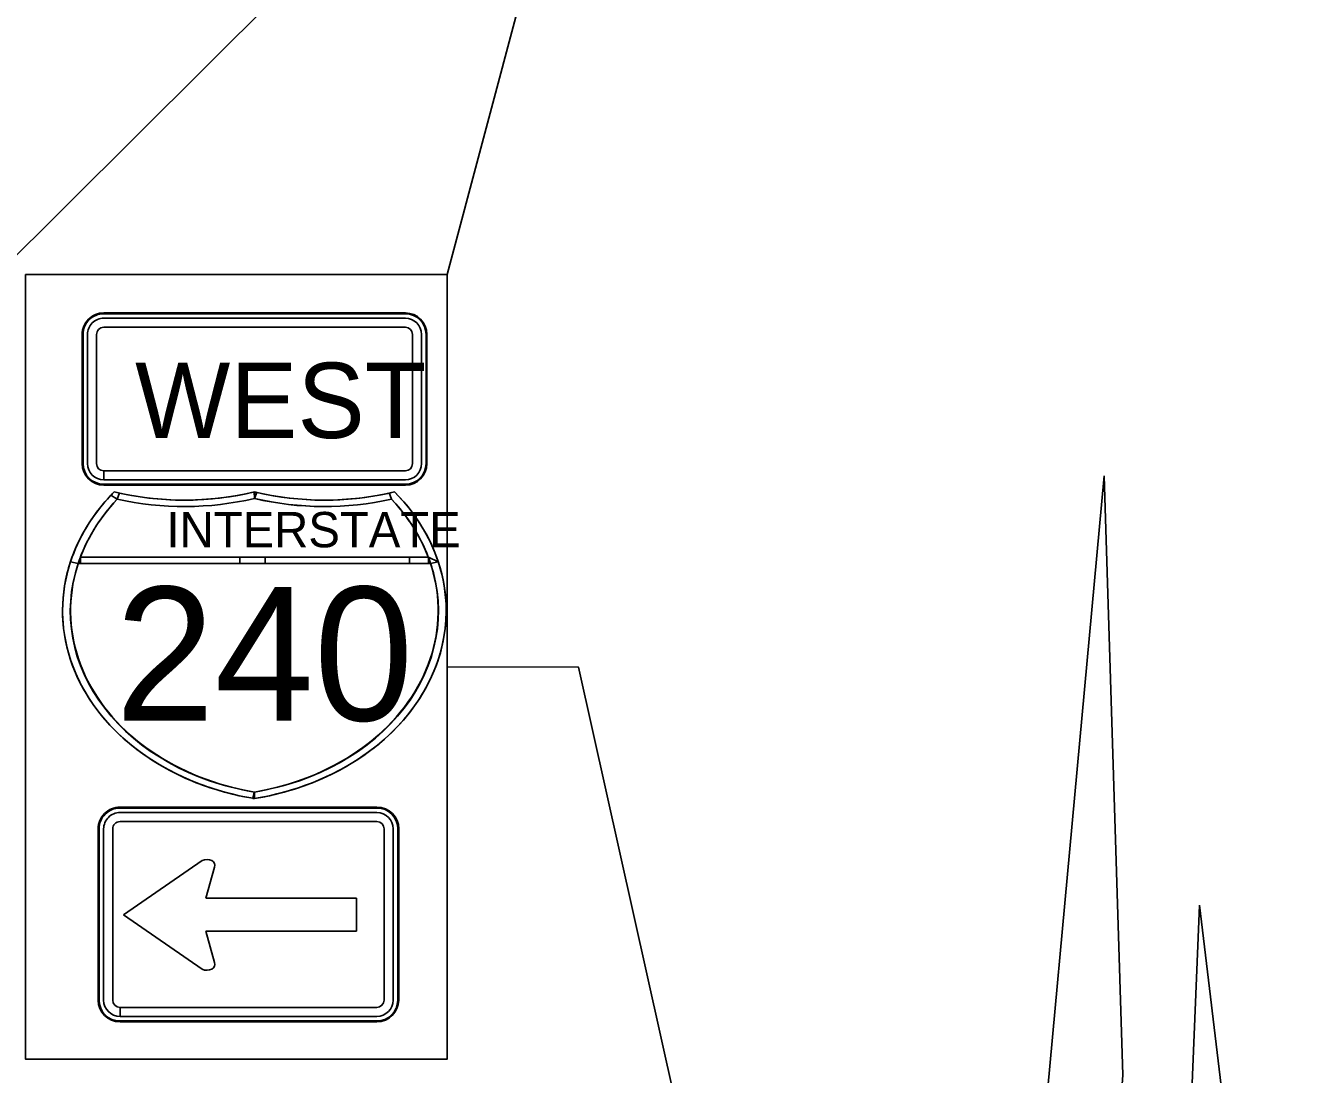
# Model space of a CAD drawing. Extents: x 886234 to 968767, y 455416 to 684046.
# Drawn here: x 915037 to 916508, y 471656 to 472874 of the extents above; entities that cross this region are included whole.
import ezdxf

# ---------------------------------------------------------------- set-up
doc = ezdxf.new("R2010")
doc.units = 0
for name, color, linetype in [('TC CONSTRUCTION PROPOSED ROADWAY SHADE', 7, 'Continuous'), ('TC DEV SIGN BLACK 239', 7, 'Continuous'), ('TC DEV SIGN BLACK ZERO', 7, 'Continuous'), ('TC DEV SIGN WHITE', 7, 'Continuous'), ('TC LABEL TEXT', 7, 'Continuous')]:
    doc.layers.add(name, color=color, linetype=linetype)

msp = doc.modelspace()

# ---------------------------------------------------------------- linework, layer by layer
at = {"layer": 'TC CONSTRUCTION PROPOSED ROADWAY SHADE'}
msp.add_lwpolyline([(915036.9, 472584.9), (915526.7, 472584.9), (915526.7, 471673.9), (915036.9, 471673.9)], close=True, dxfattribs=at)
at = {"layer": 'TC DEV SIGN BLACK 239'}
for p, q in [((915478, 472534.1), (915127.9, 472534.1)), ((915478, 472523.7), (915127.9, 472523.7)), ((915109.2, 472515.4), (915109.2, 472365.4)), ((915119.6, 472515.4), (915119.6, 472365.4)), ((915486.3, 472365.4), (915486.3, 472515.4)), ((915496.7, 472365.4), (915496.7, 472515.4)), ((915127.9, 472346.6), (915127.9, 472357)), ((915128, 472357), (915478, 472357)), ((915128, 472357), (915128, 472346.6)), ((915128, 472346.6), (915478, 472346.6)), ((915445, 471960.3), (915146.8, 471960.3)), ((915445, 471949.7), (915146.8, 471949.7)), ((915127.8, 471941.2), (915127.8, 471742.5)), ((915138.3, 471941.2), (915138.3, 471742.5)), ((915453.4, 471742.5), (915453.4, 471941.2)), ((915464, 471742.5), (915464, 471941.2)), ((915242.3, 471904.6), (915150.7, 471841.4)), ((915246.3, 471860.9), (915256.6, 471896.9)), ((915421.2, 471860.9), (915246.3, 471860.9)), ((915421.2, 471822.6), (915421.2, 471860.9)), ((915150.7, 471841.4), (915242.3, 471778.3)), ((915256.6, 471786), (915246.3, 471822.6)), ((915246.3, 471822.6), (915421.2, 471822.6)), ((915146.8, 471723.4), (915146.8, 471734)), ((915146.9, 471734), (915444.9, 471734)), ((915146.9, 471734), (915146.9, 471723.4)), ((915146.9, 471723.4), (915444.9, 471723.4))]:
    msp.add_line(p, q, dxfattribs=at)
for centre, major_axis, ratio, start_param, end_param in [((915127.9, 472515.4), (18.8, 0), 0.999865, 1.570796, 3.141593), ((915127.9, 472515.4), (8.33, 0), 0.999865, 1.570796, 3.141593), ((915478, 472515.4), (18.8, 0), 0.999865, 0, 1.570796), ((915478, 472515.4), (8.33, 0), 0.999865, 0, 1.570796), ((915127.9, 472365.4), (18.8, 0), 0.999865, 3.141593, 4.712389), ((915127.9, 472365.4), (8.33, 0), 0.999865, 3.141593, 4.712389), ((915478, 472365.4), (18.8, 0), 0.999865, 4.712389, 6.283185), ((915478, 472365.4), (8.33, 0), 0.999865, 4.712389, 6.283185), ((915146.8, 471941.2), (19, 0), 0.999865, 1.570796, 3.141593), ((915146.8, 471941.2), (8.45, 0), 0.999865, 1.570796, 3.141593), ((915445, 471941.2), (19, 0), 0.999865, 0, 1.570796), ((915445, 471941.2), (8.45, 0), 0.999865, 0, 1.570796), ((915247.6, 471899), (-9.44, 0), 0.720018, 2.830616, 5.313575), ((915247.6, 471783.9), (-9.44, 0), 0.720018, 0.969609, 3.452568), ((915146.8, 471742.5), (19, 0), 0.999865, 3.141593, 4.712389), ((915146.8, 471742.5), (8.45, 0), 0.999865, 3.141593, 4.712389), ((915444.9, 471742.5), (19, 0), 0.999865, 4.712389, 6.283185), ((915444.9, 471742.5), (8.45, 0), 0.999865, 4.712389, 6.283185)]:
    msp.add_ellipse(centre, major_axis=major_axis, ratio=ratio, start_param=start_param, end_param=end_param, dxfattribs=at)
at = {"layer": 'TC DEV SIGN BLACK ZERO'}
for p, q in [((915478, 472540.4), (915127.9, 472540.4)), ((915127.9, 472539.3), (915127.9, 472539.3)), ((915478, 472539.3), (915127.9, 472539.3)), ((915478, 472539.3), (915478, 472539.3)), ((915102.9, 472515.4), (915102.9, 472365.4)), ((915104, 472515.4), (915104, 472365.4)), ((915104, 472515.4), (915104, 472515.4)), ((915502, 472515.4), (915502, 472515.4)), ((915502, 472365.4), (915502, 472515.4)), ((915503, 472365.4), (915503, 472515.4)), ((915104, 472365.4), (915104, 472365.4)), ((915502, 472365.4), (915502, 472365.4)), ((915127.9, 472340.4), (915127.9, 472341.4)), ((915127.9, 472341.4), (915127.9, 472341.4)), ((915128, 472341.4), (915478, 472341.4)), ((915128, 472341.4), (915128, 472340.4)), ((915128, 472340.4), (915478, 472340.4)), ((915143.6, 472324.1), (915146.1, 472331.3)), ((915303, 472324.9), (915302.7, 472332.7)), ((915303, 472325.5), (915302.7, 472332.7)), ((915459.4, 472331.3), (915461.9, 472324.1)), ((915478, 472341.4), (915478, 472341.4)), ((915100.8, 472256.7), (915504.7, 472256.7)), ((915285.8, 472256.7), (915100.8, 472256.7)), ((915315.1, 472256.7), (915285.8, 472256.7)), ((915482.8, 472256.7), (915315.1, 472256.7)), ((915504.7, 472256.7), (915482.8, 472256.7)), ((915516.3, 472251.2), (915504.7, 472256.7)), ((915098.2, 472249.3), (915507.3, 472249.3)), ((915098.2, 472249.3), (915100.8, 472249.3)), ((915100.8, 472249.3), (915285.8, 472249.3)), ((915285.8, 472249.3), (915315.1, 472249.3)), ((915315.1, 472249.3), (915482.8, 472249.3)), ((915482.8, 472249.3), (915504.7, 472249.3)), ((915507.1, 472249.8), (915504.7, 472249.3)), ((915504.7, 472249.3), (915507.3, 472249.3)), ((915080.1, 472195.7), (915080.1, 472193.5)), ((915525.4, 472193.4), (915525.4, 472195.7)), ((915302.8, 471976.4), (915302.8, 471984)), ((915445, 471966.6), (915146.8, 471966.6)), ((915146.8, 471965.5), (915146.8, 471965.5)), ((915445, 471965.5), (915146.8, 471965.5)), ((915445, 471965.5), (915445, 471965.5)), ((915121.4, 471941.2), (915121.4, 471742.5)), ((915122.5, 471941.2), (915122.5, 471742.5)), ((915122.5, 471941.2), (915122.5, 471941.2)), ((915469.2, 471941.2), (915469.3, 471941.2)), ((915469.2, 471742.5), (915469.3, 471941.2)), ((915470.3, 471742.5), (915470.3, 471941.2)), ((915122.5, 471742.5), (915122.5, 471742.5)), ((915469.2, 471742.5), (915469.2, 471742.5)), ((915146.8, 471717.1), (915146.8, 471718.2)), ((915146.8, 471718.2), (915146.8, 471718.2)), ((915146.8, 471718.2), (915444.9, 471718.2)), ((915146.8, 471718.2), (915146.8, 471717.1)), ((915146.8, 471717.1), (915444.9, 471717.1)), ((915444.9, 471718.2), (915444.9, 471718.2))]:
    msp.add_line(p, q, dxfattribs=at)
for points in [[(915140.1, 472332.7), (915140.1, 472332.7), (915140.1, 472332.7)], [(915146.1, 472331.3), (915143.6, 472324.1)], [(915303, 472332.6), (915303, 472325.5), (915305.6, 472332)], [(915305.6, 472332), (915303, 472324.9)], [(915461.9, 472324.1), (915459.4, 472331.3)], [(915465.4, 472332.7), (915465.4, 472332.7), (915465.4, 472332.7)], [(915136.1, 472328.6), (915143.6, 472324.1)], [(915143.6, 472324.1), (915136.1, 472328.6)], [(915302.8, 472324.9), (915303, 472325.5)], [(915100.8, 472256.7), (915100.8, 472249.3)], [(915100.8, 472249.3), (915100.8, 472256.7)], [(915285.8, 472249.3), (915285.8, 472256.7)], [(915285.8, 472256.7), (915285.8, 472249.3)], [(915315.1, 472256.7), (915315.1, 472249.3)], [(915315.1, 472249.3), (915315.1, 472256.7)], [(915482.8, 472249.3), (915482.8, 472256.7)], [(915482.8, 472256.7), (915482.8, 472249.3)], [(915504.7, 472256.7), (915516.3, 472251.2)], [(915504.7, 472249.3), (915504.7, 472256.7)], [(915504.7, 472256.7), (915504.7, 472249.3), (915507.1, 472249.8), (915504.7, 472256.7)], [(915089.2, 472251.2), (915098.2, 472249.3)], [(915098.2, 472249.3), (915089.2, 472251.2)], [(915507.3, 472249.3), (915507.1, 472249.8)], [(915516.3, 472251.2), (915507.3, 472249.3)], [(915507.3, 472249.3), (915516.3, 472251.2)], [(915300.8, 471976.7), (915302.7, 471984)], [(915302.8, 471984), (915300.8, 471976.7), (915302.7, 471976.4)], [(915302.8, 471984), (915302.8, 471976.4)]]:
    msp.add_lwpolyline(points, dxfattribs=at)
for centre, major_axis, ratio, start_param, end_param in [((915127.9, 472515.4), (25, 0), 0.999865, 1.570796, 3.141593), ((915127.9, 472515.4), (24, 0), 0.999865, 1.570796, 3.141593), ((915478, 472515.4), (25, 0), 0.999865, 0, 1.570796), ((915478, 472515.4), (24, 0), 0.999865, 0, 1.570796), ((915127.9, 472365.4), (25, 0), 0.999865, 3.141593, 4.712389), ((915127.9, 472365.4), (24, 0), 0.999865, 3.141593, 4.712389), ((915478, 472365.4), (25, 0), 0.999865, 4.712389, 6.283185), ((915478, 472365.4), (24, 0), 0.999865, 4.712389, 6.283185), ((915358.4, 472194.6), (-278.3, 0), 0.800002, 5.614188, 7.652625), ((915358.4, 472194.6), (-278.3, 0), 0.800002, 5.614216, 5.637358), ((915221.4, 472545.6), (278.3, 0), 0.800002, 4.415792, 5.008922), ((915221.4, 472545.6), (278.3, 0), 0.800002, 4.415856, 4.438209), ((915221.4, 472545.6), (278.3, 0), 0.800002, 4.438209, 5.008909), ((915384.1, 472545.6), (278.3, 0), 0.800002, 4.415856, 5.008986), ((915247.1, 472194.6), (278.3, 0), 0.800002, 4.913746, 6.952183), ((915384.1, 472545.6), (278.3, 0), 0.800002, 4.416709, 4.426515), ((915384.1, 472545.6), (278.3, 0), 0.800002, 4.426515, 4.986569), ((915384.1, 472545.6), (278.3, 0), 0.800002, 4.986569, 5.008922), ((915247.1, 472194.6), (278.3, 0), 0.800002, 0.256966, 0.66897), ((915358.4, 472194.6), (-269, 0), 0.800002, 5.637358, 7.64558), ((915358.4, 472194.6), (-278.3, 0), 0.800002, 5.637358, 6.026219), ((915358.4, 472194.6), (-269, 0), 0.800002, 5.637358, 6.026219), ((915221.4, 472545.6), (287.6, 0), 0.800002, 4.438209, 4.999074), ((915221.4, 472545.6), (287.6, 0), 0.800002, 4.438209, 4.999074), ((915384.1, 472545.6), (287.6, 0), 0.800002, 4.425704, 4.986569), ((915247.1, 472194.6), (269, 0), 0.800002, 4.920791, 6.929013), ((915384.2, 472545.3), (287.2, 0), 0.800002, 4.425686, 4.986568), ((915247.1, 472194.6), (269, 0), 0.800002, 0.292795, 0.645828), ((915358.4, 472194.6), (-269, 0), 0.800002, 5.99039, 6.026219), ((915247.1, 472194.6), (269, 0), 0.800002, 0.256966, 0.292795), ((915357.1, 472193.9), (-268, 0), 0.800002, 6.022151, 7.649781), ((915358.4, 472194.6), (-278.3, 0), 0.800002, 6.026219, 6.278259), ((915248.4, 472193.9), (268, 0), 0.800002, 4.916934, 6.544356), ((915247.1, 472194.6), (278.3, 0), 0.800002, 0.005231, 0.256966), ((915358.4, 472194.6), (-278.3, 0), 0.800002, 0.004927, 1.362388), ((915247.1, 472194.6), (278.3, 0), 0.800002, 4.913748, 6.277955), ((915358.4, 472194.6), (-278.3, 0), 0.800002, 1.36935, 1.369438), ((915247.1, 472194.6), (269, 0), 0.800002, 4.920791, 4.921138), ((915247.1, 472194.6), (278.3, 0), 0.800002, 4.913747, 4.913748), ((915146.8, 471941.2), (25.4, 0), 0.999865, 1.570796, 3.141593), ((915146.8, 471941.2), (24.3, 0), 0.999865, 1.570796, 3.141593), ((915445, 471941.2), (25.4, 0), 0.999865, 0, 1.570796), ((915445, 471941.2), (24.3, 0), 0.999865, 0, 1.570796), ((915146.8, 471742.5), (25.4, 0), 0.999865, 3.141593, 4.712389), ((915146.8, 471742.5), (24.3, 0), 0.999865, 3.141593, 4.712389), ((915444.9, 471742.5), (25.4, 0), 0.999865, 4.712389, 6.283185), ((915444.9, 471742.5), (24.3, 0), 0.999865, 4.712389, 6.283185)]:
    msp.add_ellipse(centre, major_axis=major_axis, ratio=ratio, start_param=start_param, end_param=end_param, dxfattribs=at)
at = {"layer": 'TC DEV SIGN WHITE'}
for p, q in [((915478, 472540.4), (915127.9, 472540.4)), ((915102.9, 472515.4), (915102.9, 472365.4)), ((915503, 472365.4), (915503, 472515.4)), ((915127.9, 472340.4), (915478, 472340.4)), ((915445, 471966.6), (915146.8, 471966.6)), ((915121.4, 471941.2), (915121.4, 471742.5)), ((915470.3, 471742.5), (915470.3, 471941.2)), ((915146.8, 471717.1), (915444.9, 471717.1))]:
    msp.add_line(p, q, dxfattribs=at)
for centre, major_axis, start_param, end_param in [((915127.9, 472515.4), (25, 0), 1.570796, 3.141593), ((915478, 472515.4), (25, 0), 0, 1.570796), ((915127.9, 472365.4), (25, 0), 3.141593, 4.712389), ((915478, 472365.4), (25, 0), 4.712389, 6.283185), ((915146.8, 471941.2), (25.4, 0), 1.570796, 3.141593), ((915445, 471941.2), (25.4, 0), 0, 1.570796), ((915146.8, 471742.5), (25.4, 0), 3.141593, 4.712389), ((915444.9, 471742.5), (25.4, 0), 4.712389, 6.283185)]:
    msp.add_ellipse(centre, major_axis=major_axis, ratio=0.999865, start_param=start_param, end_param=end_param, dxfattribs=at)
at = {"layer": 'TC LABEL TEXT'}
for q in [(914547.1, 472129.4), (915526.7, 472584.9)]:
    msp.add_line((915715.4, 473294.3), q, dxfattribs=at)
msp.add_lwpolyline([(915036.9, 472584.9), (915526.7, 472584.9), (915526.7, 471673.9), (915036.9, 471673.9)], close=True, dxfattribs=at)
for points in [[(915944.3, 469983.5), (915988.5, 470213.5), (916112.2, 470682.3), (916183.5, 471203.2), (916289.2, 472351.4)], [(916289.2, 472351.4), (916310.8, 471655.2), (916244.8, 470761.9), (916138.7, 469877.4)], [(915526.7, 472129.4), (915679.2, 472128.9), (916078, 470338.3)], [(916240.8, 469828), (916258.4, 469992), (916368, 471082.2), (916399.8, 471852.6)], [(916399.8, 471852.6), (916457.1, 471375.1), (916463.5, 470910.3), (916463.5, 470547.5), (916476.2, 470241.9), (916501.6, 469949), (916508, 469745.3)]]:
    msp.add_lwpolyline(points, dxfattribs=at)

# ---------------------------------------------------------------- texts
at = {"layer": 'TC DEV SIGN BLACK 239'}
msp.add_text('WEST', height=87.5, rotation=360, dxfattribs=at).set_placement((915164.3, 472395.1))
at = {"layer": 'TC DEV SIGN BLACK ZERO'}
for s, height, p in [('INTERSTATE', 41.06, (915200.7, 472268.2)), ('240', 155.13, (915141.2, 472067.1))]:
    msp.add_text(s, height=height, rotation=360, dxfattribs=at).set_placement(p)

doc.saveas('drawing.dxf')
